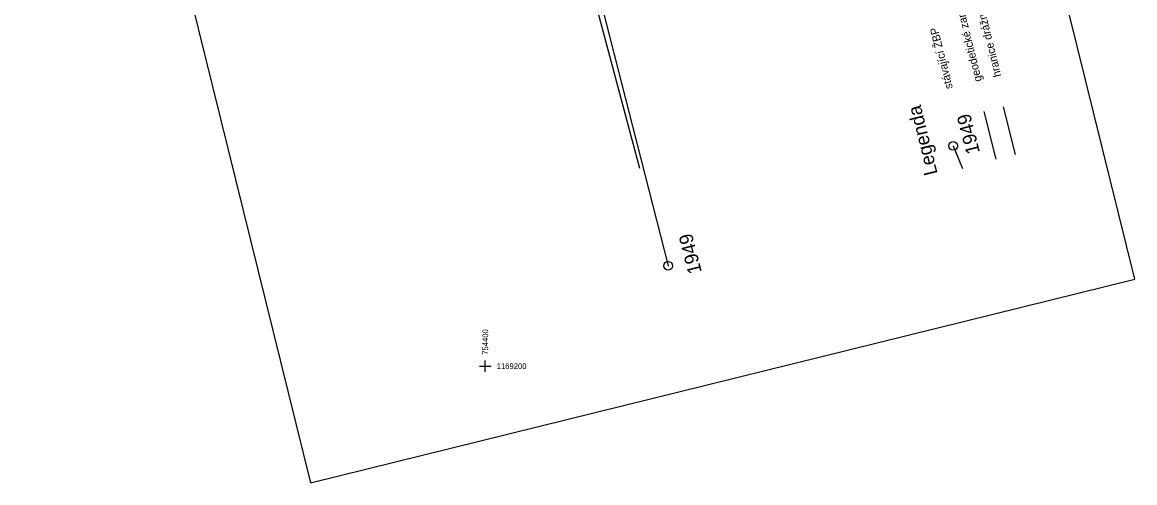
# Model space of a CAD drawing. Extents: x -754679 to -754173, y -1169241 to -1168288.
# Drawn here: x -754562 to -754172.8, y -1169240.8 to -1169079.6 of the extents above; entities that cross this region are included whole.
import ezdxf

# ---------------------------------------------------------------- set-up
doc = ezdxf.new("R2010")
doc.units = 0
for name, color, linetype in [('Default', 7, 'Continuous'), ('Vrstva 1', 7, 'Continuous'), ('Vrstva 2', 7, 'Continuous'), ('Vrstva 24', 7, 'Continuous'), ('Vrstva 27', 7, 'Continuous'), ('Vrstva 53', 7, 'Continuous'), ('Vrstva 61', 7, 'Continuous'), ('Vrstva 63', 7, 'Continuous')]:
    doc.layers.add(name, color=color, linetype=linetype)

msp = doc.modelspace()

# ---------------------------------------------------------------- linework, layer by layer
at = {"layer": 'Default'}
for points in [[(-754400, -1169202), (-754400, -1169200), (-754400, -1169198)], [(-754402, -1169200), (-754400, -1169200), (-754398, -1169200)]]:
    msp.add_lwpolyline(points, dxfattribs=at)
at = {"layer": 'Vrstva 1'}
msp.add_line((-754335.99, -1169164.84), (-754335.99, -1169164.84), dxfattribs=at)
at = {"layer": 'Vrstva 24'}
msp.add_line((-754214.56, -1169125.87), (-754218.69, -1169109.2), dxfattribs=at)
at = {"layer": 'Vrstva 27'}
msp.add_line((-754221.36, -1169127.56), (-754225.49, -1169110.88), dxfattribs=at)
at = {"layer": 'Vrstva 53'}
msp.add_lwpolyline([(-754345.91, -1169130.8), (-754386.06, -1168980.52), (-754394.57, -1168948.26)], dxfattribs=at)
at = {"layer": 'Vrstva 61'}
msp.add_line((-754561.97, -1168833.08), (-754461.15, -1169240.8), dxfattribs=at)
msp.add_lwpolyline([(-754461.15, -1169240.8), (-754172.83, -1169169.5), (-754273.65, -1168761.78), (-754561.97, -1168833.08)], dxfattribs=at)
at = {"layer": 'Vrstva 63'}
for p, q in [((-754236.38, -1169122.84), (-754236.37, -1169123.04)), ((-754336.09, -1169164.84), (-754335.89, -1169164.84))]:
    msp.add_line(p, q, dxfattribs=at)
for points in [[(-754409.15, -1168875.91), (-754380.95, -1168989.01), (-754335.99, -1169164.84)], [(-754236.38, -1169122.94), (-754233.07, -1169130.81)]]:
    msp.add_lwpolyline(points, dxfattribs=at)
for centre in [(-754236.38, -1169122.94), (-754335.99, -1169164.84)]:
    msp.add_circle(centre, 1.51, dxfattribs=at)

# ---------------------------------------------------------------- texts
at = {"layer": 'Default'}
msp.add_text('754400', height=2, rotation=90, dxfattribs=at).set_placement((-754399, -1169196))
msp.add_text('1169200', height=2, dxfattribs=at).set_placement((-754396, -1169201))
at = {"layer": 'Vrstva 2'}
for p in [(-754226.95, -1169125.13), (-754324.23, -1169167.04)]:
    msp.add_text('1949', height=4.8, rotation=104.3427, dxfattribs=at).set_placement(p)
at = {"layer": 'Vrstva 27'}
for s, height, p in [('geodetické zaměření skutečného stavu', 2.8, (-754226.28, -1169100.11)), ('hranice drážního pozemku', 2.8, (-754219.49, -1169098.43)), ('stávající ŽBP', 2.8, (-754236.47, -1169102.63)), ('Legenda', 4.8, (-754241.74, -1169132.6))]:
    msp.add_text(s, height=height, rotation=103.9106, dxfattribs=at).set_placement(p)

doc.saveas('drawing.dxf')
